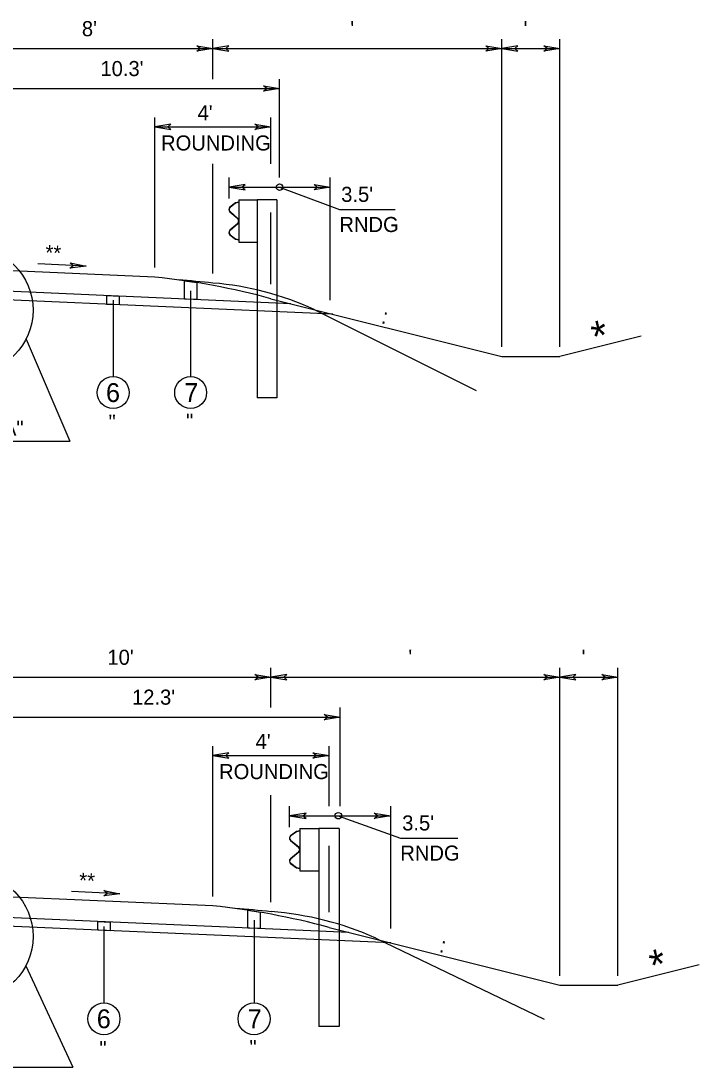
# Model space of a CAD drawing. Extents: x -540 to 1231, y -564 to 421.
# Drawn here: x 879.9 to 942.9, y 70.3 to 167.5 of the extents above; entities that cross this region are included whole.
import ezdxf

# ---------------------------------------------------------------- set-up
doc = ezdxf.new("R2010")
doc.units = 0
doc.layers.add('1', color=7, linetype='Continuous')
doc.layers.add('Des_ Drain_ Ftrs', color=7, linetype='Continuous')

msp = doc.modelspace()

# ---------------------------------------------------------------- linework, layer by layer
at = {"layer": '1'}
for p, q in [((897.731, 162.061), (897.731, 165.763)), ((924.553, 137.181), (924.553, 165.763)), ((929.942, 137.181), (929.942, 165.763)), ((876.178, 164.883), (897.731, 164.883)), ((897.731, 164.883), (924.553, 164.883)), ((924.553, 164.883), (929.942, 164.883)), ((903.923, 152.905), (903.923, 162.061)), ((876.173, 161.181), (903.923, 161.181)), ((892.342, 144.55), (892.342, 158.487)), ((903.119, 154.188), (903.119, 158.487)), ((892.342, 157.607), (903.119, 157.607)), ((897.731, 143.995), (897.731, 154.188)), ((899.231, 150.954), (899.231, 152.905)), ((908.615, 141.541), (908.615, 152.905)), ((899.231, 152.025), (908.615, 152.025)), ((903.923, 152.025), (909.48, 149.953)), ((900.143, 150.612), (899.829, 150.557)), ((900.143, 150.582), (899.841, 150.529)), ((900.143, 150.841), (900.143, 146.909)), ((900.143, 150.841), (901.828, 150.841)), ((901.828, 150.841), (901.828, 132.444)), ((903.654, 150.841), (901.828, 150.841)), ((903.654, 150.841), (903.654, 132.444)), ((899.297, 149.735), (900.028, 149.1)), ((899.829, 150.557), (899.311, 150.168)), ((899.316, 149.758), (900.047, 149.123)), ((899.841, 150.529), (899.329, 150.144)), ((903.119, 143.026), (903.119, 149.674)), ((909.48, 149.953), (914.635, 149.953)), ((900.028, 148.649), (899.297, 148.014)), ((900.047, 148.627), (899.316, 147.992)), ((900.114, 148.913), (900.114, 148.837)), ((900.143, 148.913), (900.143, 148.837)), ((899.311, 147.582), (899.829, 147.192)), ((899.329, 147.606), (899.841, 147.22)), ((899.829, 147.192), (900.143, 147.137)), ((899.841, 147.22), (900.143, 147.167)), ((900.143, 146.909), (901.828, 146.909)), ((885.957, 144.695), (881.463, 144.892)), ((892.342, 143.67), (876.183, 144.375)), ((899.231, 142.894), (899.231, 142.894)), ((904.952, 141.202), (877.825, 142.387)), ((895.663, 142.406), (895.663, 134.432)), ((908.871, 140.222), (877.825, 141.578)), ((888.467, 141.519), (888.467, 134.432)), ((903.119, 141.661), (924.553, 136.301)), ((907.115, 140.661), (922.166, 133.135)), ((937.477, 138.185), (929.942, 136.301)), ((880.378, 137.904), (884.433, 128.439)), ((924.553, 136.301), (929.942, 136.301)), ((903.654, 132.444), (901.828, 132.444)), ((865.647, 128.439), (884.433, 128.439)), ((903.119, 103.696), (903.119, 107.399)), ((929.942, 78.801), (929.942, 107.399)), ((935.33, 78.801), (935.33, 107.399)), ((876.178, 106.519), (903.119, 106.519)), ((903.119, 106.519), (929.942, 106.519)), ((929.942, 106.519), (935.33, 106.519)), ((909.546, 94.54), (909.546, 103.696)), ((876.177, 102.816), (909.546, 102.816)), ((897.731, 86.17), (897.731, 100.123)), ((908.507, 94.54), (908.507, 100.123)), ((897.731, 99.243), (908.507, 99.243)), ((903.119, 85.631), (903.119, 95.576)), ((904.854, 92.59), (904.854, 94.54)), ((914.238, 83.177), (914.238, 94.54)), ((904.854, 93.66), (914.238, 93.66)), ((909.371, 93.66), (915.136, 91.589)), ((905.801, 92.476), (905.801, 88.545)), ((905.801, 92.476), (907.549, 92.476)), ((907.549, 92.476), (907.549, 74.079)), ((909.442, 92.476), (907.549, 92.476)), ((909.442, 92.476), (909.442, 74.079)), ((904.923, 91.371), (905.682, 90.736)), ((905.475, 92.192), (904.938, 91.803)), ((904.943, 91.394), (905.701, 90.758)), ((905.487, 92.164), (904.957, 91.78)), ((905.801, 92.248), (905.475, 92.192)), ((905.801, 92.218), (905.487, 92.164)), ((915.136, 91.589), (920.483, 91.589)), ((905.77, 90.548), (905.77, 90.473)), ((905.801, 90.548), (905.801, 90.473)), ((908.507, 84.718), (908.507, 90.868)), ((905.682, 90.285), (904.923, 89.65)), ((905.701, 90.263), (904.943, 89.627)), ((904.938, 89.218), (905.475, 88.828)), ((904.957, 89.241), (905.487, 88.856)), ((905.475, 88.828), (905.801, 88.772)), ((905.487, 88.856), (905.801, 88.803)), ((905.801, 88.545), (907.549, 88.545)), ((889.089, 86.414), (884.595, 86.611)), ((897.731, 85.29), (876.183, 86.231)), ((904.854, 84.53), (904.854, 84.53)), ((910.34, 82.823), (877.825, 84.242)), ((901.549, 83.976), (901.549, 76.287)), ((914.26, 81.842), (877.825, 83.433)), ((887.612, 83.366), (887.612, 76.287)), ((908.507, 83.281), (929.942, 77.921)), ((912.858, 82.297), (928.47, 74.771)), ((880.356, 79.717), (884.71, 70.321)), ((942.865, 79.805), (935.33, 77.921)), ((929.942, 77.921), (935.33, 77.921)), ((909.442, 74.079), (907.549, 74.079)), ((865.924, 70.321), (884.71, 70.321))]:
    msp.add_line(p, q, dxfattribs=at)
for points in [[(895.09, 143.329), (896.236, 143.153), (896.236, 141.583), (895.09, 141.633)], [(887.893, 141.947), (889.04, 141.897), (889.04, 141.088), (887.893, 141.138)], [(900.976, 84.876), (902.123, 84.691), (902.123, 83.181), (900.976, 83.232)], [(887.039, 83.84), (888.186, 83.79), (888.186, 82.981), (887.039, 83.031)]]:
    msp.add_lwpolyline(points, close=True, dxfattribs=at)
for centre, radius in [((903.922, 152.025), 0.3), ((875.199, 140.598), 5.838), ((888.467, 132.946), 1.485), ((895.663, 132.946), 1.485), ((875.199, 82.453), 5.838), ((887.612, 74.802), 1.485), ((901.549, 74.802), 1.485)]:
    msp.add_circle(centre, radius, dxfattribs=at)
for centre, radius, start, end in [((899.479, 149.945), 0.278, 126.97989, 229.02099), ((899.479, 149.945), 0.249, 126.97989, 229.02099), ((899.865, 148.913), 0.249, 0, 49.03649), ((899.865, 148.837), 0.249, 310.96352, 0), ((899.865, 148.913), 0.278, 0, 49.03649), ((899.865, 148.837), 0.278, 310.96352, 0), ((899.479, 147.804), 0.278, 130.97902, 233.02011), ((899.479, 147.804), 0.249, 130.97902, 233.02011), ((885.458, 76.836), 67.188, 74.76019, 84.11876), ((886.908, 42.451), 101.244, 83.86333, 85.67746), ((895.608, 115.829), 27.368, 65.13739, 85.55132), ((890.846, 18.456), 67.188, 74.76019, 84.11876)]:
    msp.add_arc(centre, radius, start, end, dxfattribs=at)
msp.add_ellipse((909.371, 93.66), major_axis=(-0.311, 0), ratio=0.964041, dxfattribs=at)
for centre, major_axis, start_param, end_param in [((905.112, 91.581), (-0.288, 0), 5.35781, 7.138763), ((905.112, 91.581), (-0.258, 0), 5.35781, 7.138763), ((905.513, 90.548), (0.258, 0), 0, 0.855848), ((905.513, 90.472), (0.258, 0), 5.427337, 6.283185), ((905.513, 90.548), (0.288, 0), 0, 0.855848), ((905.513, 90.472), (0.288, 0), 5.427337, 6.283185), ((905.112, 89.44), (-0.288, 0), 5.427608, 7.208561), ((905.112, 89.44), (-0.258, 0), 5.427608, 7.208561), ((891.897, -15.913), (105.02, 0), 1.463691, 1.495354), ((900.922, 57.465), (28.389, 0), 1.136862, 1.493152)]:
    msp.add_ellipse(centre, major_axis=major_axis, ratio=0.964041, start_param=start_param, end_param=end_param, dxfattribs=at)
at = {"layer": 'Des_ Drain_ Ftrs'}
for points in [[(897.731, 164.883), (896.242, 164.634), (896.537, 164.883), (896.242, 165.131)], [(897.731, 164.883), (899.219, 164.634), (898.924, 164.883), (899.219, 165.131)], [(924.553, 164.883), (923.065, 164.634), (923.36, 164.883), (923.065, 165.131)], [(924.553, 164.883), (926.042, 164.634), (925.747, 164.883), (926.042, 165.131)], [(929.942, 164.883), (928.453, 164.634), (928.748, 164.883), (928.453, 165.131)], [(903.923, 161.181), (902.434, 160.932), (902.729, 161.181), (902.434, 161.429)], [(892.342, 157.607), (893.831, 157.359), (893.536, 157.607), (893.831, 157.855)], [(903.119, 157.607), (901.631, 157.359), (901.926, 157.607), (901.631, 157.855)], [(899.231, 152.025), (900.719, 151.776), (900.424, 152.025), (900.719, 152.273)], [(908.615, 152.025), (907.126, 151.776), (907.421, 152.025), (907.126, 152.273)], [(885.957, 144.695), (884.459, 144.511), (884.765, 144.746), (884.481, 145.007)], [(903.119, 106.519), (901.63, 106.27), (901.925, 106.519), (901.63, 106.767)], [(903.119, 106.519), (904.607, 106.27), (904.312, 106.519), (904.607, 106.767)], [(929.942, 106.519), (928.454, 106.27), (928.749, 106.519), (928.454, 106.767)], [(929.942, 106.519), (931.431, 106.27), (931.136, 106.519), (931.431, 106.767)], [(935.33, 106.519), (933.842, 106.27), (934.137, 106.519), (933.842, 106.767)], [(909.546, 102.816), (908.057, 102.568), (908.352, 102.816), (908.057, 103.065)], [(897.731, 99.243), (899.219, 98.994), (898.924, 99.243), (899.219, 99.491)], [(908.507, 99.243), (907.019, 98.994), (907.314, 99.243), (907.019, 99.491)], [(904.854, 93.66), (906.398, 93.412), (906.092, 93.66), (906.398, 93.909)], [(914.238, 93.66), (912.695, 93.412), (913.001, 93.66), (912.695, 93.909)], [(889.089, 86.414), (887.591, 86.23), (887.896, 86.466), (887.612, 86.726)]]:
    msp.add_lwpolyline(points, close=True, dxfattribs=at)

# ---------------------------------------------------------------- texts
at = {"layer": '1'}
for s, height, p in [("8'", 1.4, (885.564, 166.034)), ("  '", 1.4, (909.446, 166.034)), (" '", 1.4, (926.052, 166.034)), ("10.3'", 1.4, (887.286, 162.332)), ("4'", 1.4, (896.302, 158.223)), ('ROUNDING', 1.4, (892.913, 155.423)), ("3.5'", 1.4, (909.639, 150.653)), ('RNDG', 1.4, (909.469, 147.853)), ('6', 1.75, (887.802, 132.072)), ('7', 1.75, (895.072, 132.072)), ('SEE DETAIL "A"', 1.4, (866.231, 128.943)), (' "', 1.4, (887.523, 129.491)), (' "', 1.4, (894.719, 129.587)), ("10'", 1.4, (887.933, 107.67)), ("  '", 1.4, (914.834, 107.67)), (" '", 1.4, (931.441, 107.67)), ("12.3'", 1.4, (890.218, 103.967)), ("4'", 1.4, (901.69, 99.858)), ('ROUNDING', 1.4, (898.301, 97.058)), ("3.5'", 1.4, (915.301, 92.289)), ('RNDG', 1.4, (915.125, 89.489)), ('6', 1.75, (886.947, 73.927)), ('7', 1.75, (900.959, 73.927)), (' "', 1.4, (886.669, 71.346)), (' "', 1.4, (900.606, 71.443))]:
    msp.add_text(s, height=height, dxfattribs=at).set_placement(p)
for s, height, rotation, p in [('**', 1.4, 357.2161, (882.143, 145.256)), (' : ', 1.4, 345.77179, (912.786, 139.533)), ('*', 2.8, 12.84793, (933.257, 136.706)), ('**', 1.4, 357.21596, (885.274, 86.975)), (' : ', 1.4, 345.77179, (918.175, 81.153)), ('*', 2.8, 12.84793, (938.645, 78.326))]:
    msp.add_text(s, height=height, rotation=rotation, dxfattribs=at).set_placement(p)

doc.saveas('drawing.dxf')
